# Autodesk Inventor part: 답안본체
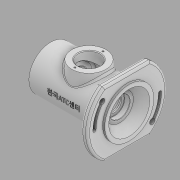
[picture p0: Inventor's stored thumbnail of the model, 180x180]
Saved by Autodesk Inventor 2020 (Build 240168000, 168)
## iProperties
Created: 2022-05
Part Number: 답안본체
Material: 일반
Document SubType Name: Modeling
Designer: Student
Density: 1 g/cm^3
Appearance: 기본값
Author: Student
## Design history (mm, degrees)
sketch "스케치1"
  geometry: L1 (-55.779, 0)-(55.779, 0); L2 (-51, 32)-(-51, 22.5); L3 (-51, 22.5)-(-43, 22.5); L4 (-43, 22.5)-(-43, 24); L5 (-43, 24)-(-40, 24); L6 (-40, 24)-(-40, 22.5); L7 (-40, 22.5)-(-29, 22.5); L8 (-29, 22.5)-(-29, 17.5); L9 (-29, 17.5)-(-26.75, 17.5); L10 (-26.75, 17.5)-(-26.75, 18.5); L11 (-26.75, 18.5)-(-25, 18.5); L12 (-25, 18.5)-(-25, 17.5); L13 (-25, 17.5)-(-14, 17.5); L14 (-14, 17.5)-(-14, 27); L15 (-14, 27)-(24, 27); L16 (24, 27)-(24, 17.5); L17 (24, 17.5)-(35, 17.5); L18 (35, 17.5)-(35, 15); L19 (35, 15)-(40, 15); L20 (40, 15)-(40, 11); L21 (40, 11)-(42, 11); L22 (42, 11)-(42, 15); L23 (42, 15)-(49.3, 15); L24 (64, 30)-(64, 36); L25 (64, 36)-(61, 36); L26 (61, 36)-(61, 58); L27 (61, 58)-(51, 58); L28 (51, 58)-(51, 32); L29 (51, 32)-(-51, 32); L30 (50, 20)-(64, 30); L31 (50, 20)-(50, 15.404); L32 (50, 15.404)-(49.3, 15); 3 further points
  constraints: 64 end point, 21 perpendicular, 7 point on line, 2 horizontal, 2 midpoint, 2 vertical, 1 coincident, 1 parallel, 1 vertical alignment
  dimensions: "d0" = 102 distance of L28.end L2.start; "d1" = 13 distance from line of L24.end L28; "d2" = 3 distance of L24.end L25.end; "d3" = 22 diameter of L21 L1; "d4" = 45 diameter of L3 L1; "d5" = 3 distance of L4.end L5.end; "d6" = 35 diameter of L13 L1; "d7" = 8 distance of L2.end L3.end; "d8" = 54 diameter of L15 L1; "d9" = 30 diameter of L23 L1; "d10" = 40 diameter of L30.start L1; "d11" = 60 diameter of L24.start L1; "d13" = 22 distance of L7.end L2.end; "d14" = 64 distance of L17.end L8.end; "d15" = 48 diameter of L5 L1; "d16" = 64 diameter of L29 L1; "d19" = 1.75 distance of L10.end L11.end; "d20" = 37 diameter of L11 L1; "d22" = 11 distance of L12.end L13.end; "d25" = 38 distance of L13.end L16.end; "d26" = 4 distance from line of L8.end L12; "d27" = 7.3 distance of L22.end L23.end; "d28" = 5 distance of L18.end L19.end; "d30" = 9.5 distance of L15.end L16.end; "d31" = 30 deg angle of L23 L32; "d32" = 0.7 horizontal distance of L31.end L23.end; "d33" = 14 distance between parallel lines of L24 L31; "d34" = 116 diameter of L27 L1; "d36" = 8.22142 distance from line of L1.end L24; "d37" = 72 diameter of L25 L1
revolve "회전1" sketch "스케치1" stored, may be unused: angle "d38" = 90 deg
sketch "스케치2"
  geometry: L1 (-33.985, 47)-(33.985, 47); L2 (-33.985, -47)-(33.985, -47); A1 r 58 centre (0, 0) between (-33.985, 47) and (33.985, 47) reference; A2 r 58 centre (0, 0) between (33.985, 47) and (-33.985, 47); A3 r 58 centre (0, 0) between (-33.985, -47) and (33.985, -47); 1 further point
  constraints: 9 point on circle, 4 end point, 2 centre point, 2 concentric, 2 horizontal
  dimensions: "d39" = 94 distance between parallel lines of L2 L1; "d40" = 47 distance from line of point (0, 0) L1
extrude "돌출1" cut sketch "스케치2" distance "d41" = 10; taper "d42" = 0 deg
sketch "스케치3"
  geometry: L1 (-68.074, 0)-(68.074, 0); L2 (-55.548, 46.61)-(55.548, -46.61); C1 r 15 at (0, 0) reference; A1 r 48 centre (0, 0) between (-48, 0) and (-34.115, -33.766); A2 r 48 centre (0, 0) between (-48, 0) and (-34.115, -33.766); A3 r 48 centre (0, 0) between (48, 0) and (36, 31.749); A4 r 48 centre (0, 0) between (-36.77, 30.854) and (-48, 0); A5 r 50.25 centre (0, 0) between (-38.494, 32.3) and (-50.25, 0); A6 r 45.75 centre (0, 0) between (-35.047, 29.408) and (-45.75, 0); A7 r 2.25 centre (-36.77, 30.854) between (-35.047, 29.408) and (-38.494, 32.3); A8 r 2.25 centre (-48, 0) between (-50.25, 0) and (-45.75, 0); A9 r 48 centre (0, 0) between (36.77, -30.854) and (48, 0); A10 r 50.25 centre (0, 0) between (38.494, -32.3) and (50.25, 0); A11 r 45.75 centre (0, 0) between (35.047, -29.408) and (45.75, 0); A12 r 2.25 centre (36.77, -30.854) between (35.047, -29.408) and (38.494, -32.3); A13 r 2.25 centre (48, 0) between (50.25, 0) and (45.75, 0); 4 further points
  constraints: 30 point on circle, 13 centre point, 10 tangent, 4 coincident, 4 concentric, 4 end point, 2 horizontal alignment, 2 midpoint, 2 point on line, 1 horizontal
  dimensions: "d43" = 96 diameter of A1; "d46" = 40 deg angle of L1 L2; "d47" = 2.25 radius of A7; "d48" = 2.25 radius of A12
extrude "돌출2" cut sketch "스케치3" distance "d49" = 10; taper "d50" = 0 deg
sketch "스케치4"
  geometry: A1 r 2.25 centre (48, 0) between (45.75, 0) and (50.25, 0) reference; A2 r 2.25 centre (36.77, 30.854) between (38.494, 32.3) and (35.047, 29.408) reference; A3 r 48 centre (0, 0) between (48, 0) and (36.77, 30.854); A4 r 52 centre (0, 0) between (52, 0) and (39.834, 33.425); A5 r 44 centre (0, 0) between (44, 0) and (33.706, 28.283); A6 r 4 centre (48, 0) between (44, 0) and (52, 0); A7 r 4 centre (36.77, 30.854) between (39.834, 33.425) and (33.706, 28.283); A8 r 2.25 centre (-48, 0) between (-45.75, 0) and (-50.25, 0) reference; A9 r 2.25 centre (-36.77, -30.854) between (-38.494, -32.3) and (-35.047, -29.408) reference; A10 r 48 centre (0, 0) between (-48, 0) and (-36.77, -30.854); A11 r 52 centre (0, 0) between (-52, 0) and (-39.834, -33.425); A12 r 44 centre (0, 0) between (-44, 0) and (-33.706, -28.283); A13 r 4 centre (-48, 0) between (-44, 0) and (-52, 0); A14 r 4 centre (-36.77, -30.854) between (-39.834, -33.425) and (-33.706, -28.283); 1 further point
  constraints: 20 point on circle, 10 centre point, 8 tangent
  dimensions: "d51" = 48 radius of A3; "d52" = 4 radius of A6; "d53" = 4 radius of A13; "d54" = 44 radius of A12
extrude "돌출3" cut sketch "스케치4" distance "d55" = 4.4; taper "d56" = 0 deg
sketch "스케치5"
  geometry: A1 r 2.25 centre (36.77, 30.854) between (38.494, 32.3) and (35.047, 29.408) reference; A2 r 4 centre (-36.77, -30.854) between (-39.834, -33.425) and (-33.706, -28.283) reference; 3 further points
  constraints: 2 coincident
hole "구멍1" sketch "스케치5" at (36.77, 30.854), (-36.77, -30.854) diameter "d57" = 8; stored, may be unused: countersink angle "d61" = 90 deg, drill point angle "d63" = 118 deg; dims "d58" = 4, "d59" = 4, "d60" = 2, "d62" = 6
node "작업 평면1"
sketch "스케치6"
  geometry: L1 (51, 32)-(51, -32) reference; C1 r 25 at (-5, 0); 1 further point
  constraints: 1 centre point, 1 horizontal alignment
  dimensions: "d66" = 25 radius of C1; "d67" = 56 distance from line of L1 C1.centre
extrude "돌출4" join sketch "스케치6" stored distance "d68" = 4.4; taper "d69" = 5 deg
sketch "스케치7"
  geometry: C1 r 16 at (0, 0); C2 r 25 at (0, 0) reference; 1 further point
  constraints: 1 centre point, 1 concentric
  dimensions: "d70" = 16 radius of C1
extrude "돌출5" cut sketch "스케치7" distance "d71" = 30; taper "d72" = 0 deg
sketch "스케치8"
  geometry: C1 r 16 at (0, 0) reference; A1 r 20.5 centre (0, 0) between (0, 20.5) and (0, -20.5); 1 further point
  constraints: 2 point on circle, 2 vertical alignment, 1 centre point, 1 coincident
  dimensions: "d73" = 41 diameter of A1
hole "구멍2" sketch "스케치8" at (0, 20.5), (0, -20.5) diameter "d74" = 2.459; stored, may be unused: countersink angle "d78" = 82 deg, drill point angle "d80" = 118 deg; dims "d75" = 6, "d76" = 3.023, "d77" = 2, "d79" = 8
fillet "모깎기1" dims "d81" = 0.6
fillet "모깎기2" dims "d82" = 0.5
fillet "모깎기3" dims "d83" = 3
chamfer "모따기1" distance "d84" = 1; stored, may be unused: second distance "d85" = 2, angle "d86" = 45 deg
node "작업 평면2"
sketch "스케치10"
  geometry: L1 (-16.105, -2.106)-(16.105, -2.106); L2 (16.105, -2.106)-(16.105, 2.106); L3 (16.105, 2.106)-(-16.105, 2.106); L4 (-16.105, 2.106)-(-16.105, -2.106); 2 further points
  constraints: 1 horizontal alignment, 1 midpoint, 2 other
feature "엠보싱1" sketch "스케치10" dims "d0" = 102, "d1" = 13, "d2" = 3, "d3" = 22, "d4" = 45, "d5" = 3, "d6" = 35, "d7" = 8, "d8" = 54, "d9" = 30, "d10" = 40, "d11" = 60, "d13" = 22, "d14" = 64, "d15" = 48, "d16" = 64, "d19" = 1.75, "d20" = 37, "d22" = 11, "d25" = 38, "d26" = 4, "d27" = 7.3, "d28" = 5, "d30" = 9.5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
node "솔리드1"
feature "A9D066F2-1C7D-4E18-AEED-F7BC21143FA4" dims "d57" = 8, "d58" = 4, "d59" = 4, "d60" = 2, "d61" = 90 deg, "d62" = 6, "d63" = 118 deg
other parameters: "d64" = 38
